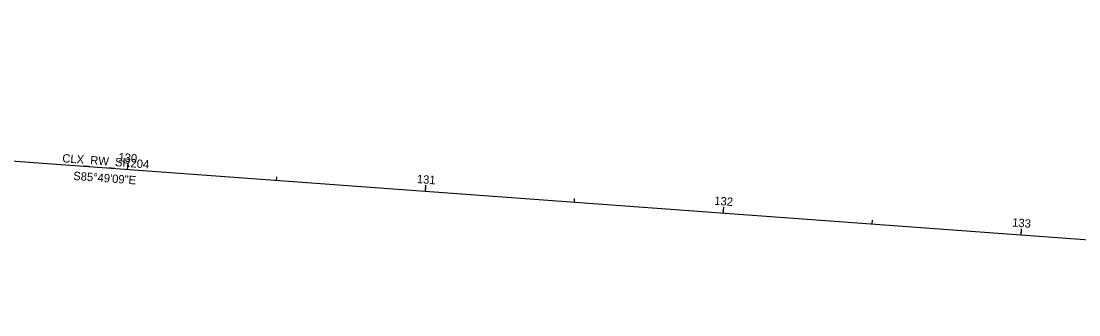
# Model space of a CAD drawing. Extents: x 1898401 to 1901169, y 703131 to 703379.
# Drawn here: x 1900460.2 to 1900814.4, y 703131.4 to 703229.8 of the extents above; entities that cross this region are included whole.
import ezdxf

# ---------------------------------------------------------------- set-up
doc = ezdxf.new("R2010")
doc.units = 0
for name, color, linetype in [('RW_X_CL', 7, 'Continuous'), ('RW_X_CL_1000_Bearings', 7, 'Continuous'), ('RW_X_CL_1000_Distances', 7, 'Continuous'), ('RW_X_CL_1000_Stations', 7, 'Continuous'), ('RW_X_CL_100_Bearings', 7, 'Continuous'), ('RW_X_CL_100_Distances', 7, 'Continuous'), ('RW_X_CL_100_Stations', 7, 'Continuous'), ('RW_X_CL_500_Bearings', 7, 'Continuous'), ('RW_X_CL_500_Distances', 7, 'Continuous'), ('RW_X_CL_500_Stations', 7, 'Continuous')]:
    doc.layers.add(name, color=color, linetype=linetype)

msp = doc.modelspace()

# ---------------------------------------------------------------- linework, layer by layer
at = {"layer": 'RW_X_CL'}
msp.add_line((1899815.76, 703229.84), (1901162.17, 703131.42), dxfattribs=at)
at = {"layer": 'RW_X_CL_1000_Stations'}
msp.add_line((1900495.85, 703180.13), (1900495.99, 703182.12), dxfattribs=at)
at = {"layer": 'RW_X_CL_100_Stations'}
for p, q in [((1900495.85, 703180.13), (1900495.99, 703182.12)), ((1900545.71, 703176.48), (1900545.8, 703177.68)), ((1900595.58, 703172.84), (1900595.73, 703174.83)), ((1900645.45, 703169.19), (1900645.53, 703170.39)), ((1900695.31, 703165.54), (1900695.46, 703167.54)), ((1900745.18, 703161.9), (1900745.27, 703163.1)), ((1900795.05, 703158.25), (1900795.19, 703160.25))]:
    msp.add_line(p, q, dxfattribs=at)
at = {"layer": 'RW_X_CL_500_Stations'}
for p, q in [((1900495.85, 703180.13), (1900495.99, 703182.12)), ((1900595.58, 703172.84), (1900595.67, 703174.03)), ((1900695.31, 703165.54), (1900695.4, 703166.74)), ((1900795.05, 703158.25), (1900795.14, 703159.45))]:
    msp.add_line(p, q, dxfattribs=at)

# ---------------------------------------------------------------- texts
at = {"layer": 'RW_X_CL_1000_Bearings'}
msp.add_text('S85°49\'09"E', height=2.8, rotation=355.8192, dxfattribs=at).set_placement((1900477.57, 703176.65))
at = {"layer": 'RW_X_CL_1000_Distances'}
msp.add_text('CLX_RW_SR204', height=2.8, rotation=355.8192, dxfattribs=at).set_placement((1900473.91, 703182.56))
at = {"layer": 'RW_X_CL_1000_Stations'}
msp.add_text('130', height=2.8, rotation=355.8192, dxfattribs=at).set_placement((1900492.69, 703182.91))
at = {"layer": 'RW_X_CL_100_Bearings'}
msp.add_text('S85°49\'09"E', height=2.8, rotation=355.8192, dxfattribs=at).set_placement((1900477.57, 703176.65))
at = {"layer": 'RW_X_CL_100_Distances'}
msp.add_text('CLX_RW_SR204', height=2.8, rotation=355.8192, dxfattribs=at).set_placement((1900473.91, 703182.56))
at = {"layer": 'RW_X_CL_100_Stations'}
for s, p in [('130', (1900492.69, 703182.91)), ('131', (1900592.62, 703175.6)), ('132', (1900692.23, 703168.32)), ('133', (1900791.97, 703161.03))]:
    msp.add_text(s, height=2.8, rotation=355.8192, dxfattribs=at).set_placement(p)
at = {"layer": 'RW_X_CL_500_Bearings'}
msp.add_text('S85°49\'09"E', height=2.8, rotation=355.8192, dxfattribs=at).set_placement((1900477.57, 703176.65))
at = {"layer": 'RW_X_CL_500_Distances'}
msp.add_text('CLX_RW_SR204', height=2.8, rotation=355.8192, dxfattribs=at).set_placement((1900473.91, 703182.56))
at = {"layer": 'RW_X_CL_500_Stations'}
msp.add_text('130', height=2.8, rotation=355.8192, dxfattribs=at).set_placement((1900492.69, 703182.91))

doc.saveas('drawing.dxf')
